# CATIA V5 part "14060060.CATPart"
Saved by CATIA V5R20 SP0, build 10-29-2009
Part number: 14060060
Definition: NONE
Nomenclature: 14060060
Source: Unknown
Description: 14060060
Bounding box of the stored display mesh (mm): x -30 to 120, y -44 to 33.913, z -34.1 to 34.1
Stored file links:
  C:\Users\Utente\Desktop\IO LAVORO\3D X SITO CF\X SITO\PLASTICA\RF2\14060060.CATPart
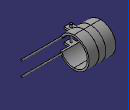
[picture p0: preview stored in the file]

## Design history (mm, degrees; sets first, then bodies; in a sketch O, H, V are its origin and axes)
Body1 "14060060" (main body)
  Solid1: solid without history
